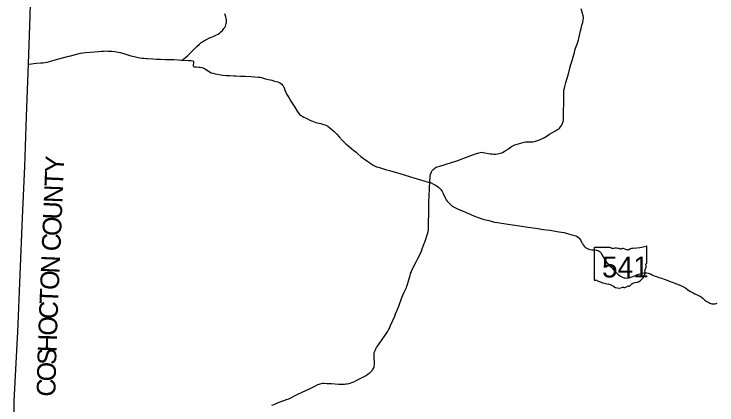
# Model space of a CAD drawing. Extents: x 1913970 to 2276415, y 78841 to 927181.
# Drawn here: x 2053316 to 2090901, y 816112 to 837024 of the extents above; entities that cross this region are included whole.
import ezdxf

# ---------------------------------------------------------------- set-up
doc = ezdxf.new("R2010")
doc.units = 0
for name, color, linetype in [('GM_X_County', 7, 'Continuous'), ('GM_X_County_Text', 7, 'Continuous'), ('GM_X_State_Location', 7, 'Continuous'), ('GM_X_State_Route', 7, 'Continuous'), ('GM_X_State_Shield', 7, 'Continuous')]:
    doc.layers.add(name, color=color, linetype=linetype)

msp = doc.modelspace()

# ---------------------------------------------------------------- linework, layer by layer
at = {"layer": 'GM_X_County'}
msp.add_lwpolyline([(2053316, 815692), (2053322, 816320), (2053497, 819709), (2053518, 820007), (2053767, 826144), (2053891, 828875), (2053973, 831537), (2054094, 834355), (2054174, 836926), (2054221, 838228)], dxfattribs=at)
at = {"layer": 'GM_X_State_Route'}
for points in [[(2062328, 834559), (2062398, 834622), (2062467, 834679), (2062601, 834812), (2062783, 834988), (2062951, 835153), (2063089, 835286), (2063229, 835416), (2063323, 835495), (2063385, 835540), (2063472, 835598), (2063563, 835650), (2063638, 835689), (2063768, 835748), (2063956, 835825), (2064140, 835905), (2064231, 835954), (2064294, 835996), (2064381, 836067), (2064455, 836140), (2064541, 836243), (2064584, 836309), (2064619, 836382), (2064643, 836450), (2064663, 836523), (2064669, 836578), (2064676, 836661), (2064672, 836720), (2064662, 836776), (2064635, 836879), (2064592, 837027)], [(2082484, 830928), (2082535, 830985), (2082589, 831056), (2082610, 831094), (2082639, 831150), (2082660, 831214), (2082678, 831279), (2082689, 831361), (2082691, 831457), (2082697, 831769), (2082705, 831966), (2082710, 832120), (2082713, 832392), (2082711, 832724), (2082713, 832834), (2082720, 832923), (2082733, 832999), (2082749, 833068), (2082770, 833147), (2082830, 833365), (2082963, 833834), (2083024, 834052), (2083097, 834321), (2083160, 834541), (2083227, 834788), (2083277, 834974), (2083305, 835071), (2083347, 835196), (2083445, 835472), (2083494, 835643), (2083515, 835722), (2083553, 835879), (2083607, 836133), (2083636, 836248), (2083685, 836424), (2083726, 836575), (2083752, 836716), (2083759, 836787), (2083759, 836845), (2083748, 836925), (2083647, 837301)], [(2054095, 834352), (2054245, 834366), (2054371, 834375), (2054516, 834389), (2054746, 834407), (2054852, 834417), (2054968, 834432), (2055085, 834458), (2055211, 834487), (2055341, 834522), (2055462, 834556), (2055648, 834606), (2056249, 834765), (2056359, 834793), (2056538, 834842), (2056862, 834923), (2056987, 834949), (2057138, 834967), (2057392, 834988), (2057610, 835003), (2057833, 835019), (2057993, 835035), (2058107, 835044), (2058202, 835048), (2058347, 835047), (2058448, 835041), (2058559, 835030), (2058706, 835012), (2058891, 834984), (2058997, 834961), (2059180, 834910), (2059461, 834825), (2059567, 834794), (2059652, 834771), (2059738, 834750), (2059816, 834729), (2059944, 834696), (2060036, 834679), (2060149, 834666), (2060262, 834656), (2060403, 834649), (2060458, 834645), (2060752, 834629), (2060935, 834617), (2061144, 834607), (2061418, 834601), (2061609, 834594), (2061858, 834584), (2062095, 834571), (2062246, 834564), (2062328, 834559)], [(2062328, 834559), (2062646, 834541), (2062793, 834533), (2062869, 834527), (2062901, 834514)], [(2062901, 834514), (2062910, 834475), (2062907, 834392), (2062895, 834299), (2062897, 834254), (2062907, 834228)], [(2062907, 834228), (2062930, 834205), (2062967, 834197), (2063062, 834193), (2063191, 834186), (2063275, 834176), (2063367, 834158), (2063438, 834135), (2063492, 834109), (2063560, 834067), (2063698, 833979), (2063775, 833931), (2063862, 833884), (2063954, 833853), (2064063, 833826), (2064181, 833803), (2064366, 833779), (2064485, 833762), (2064675, 833743), (2064856, 833733), (2065068, 833722), (2065183, 833716), (2065430, 833707), (2065683, 833697), (2065980, 833683), (2066198, 833669), (2066367, 833656), (2066469, 833640), (2066542, 833626), (2066659, 833595), (2066765, 833566), (2066903, 833531), (2067023, 833500), (2067108, 833480), (2067248, 833440), (2067424, 833390), (2067515, 833357), (2067569, 833327), (2067630, 833277), (2067671, 833228), (2067709, 833177), (2067744, 833109), (2067772, 833030), (2067818, 832900), (2067844, 832839), (2067904, 832724), (2068001, 832560), (2068122, 832367), (2068333, 832041), (2068462, 831836), (2068551, 831703), (2068586, 831657), (2068631, 831613), (2068664, 831589), (2068715, 831562), (2068813, 831513), (2068905, 831468), (2069038, 831398), (2069172, 831330), (2069270, 831287), (2069355, 831254), (2069445, 831227), (2069712, 831161), (2069809, 831138), (2069941, 831098), (2070015, 831064), (2070089, 831020), (2070177, 830957), (2070328, 830832), (2070415, 830755), (2070576, 830592), (2070699, 830459), (2070862, 830282), (2070982, 830161), (2071062, 830086), (2071149, 830009), (2071251, 829926), (2071359, 829837), (2071493, 829728), (2071607, 829630), (2071702, 829547), (2071861, 829412), (2071998, 829301), (2072109, 829219), (2072239, 829131), (2072394, 829025), (2072488, 828963), (2072568, 828918), (2072630, 828886), (2072693, 828859), (2072792, 828825), (2072911, 828789), (2073179, 828711), (2073401, 828650), (2073567, 828602), (2073893, 828506), (2074229, 828403), (2074454, 828337), (2074572, 828301), (2074686, 828266), (2074870, 828210), (2075050, 828158), (2075181, 828117), (2075287, 828086), (2075398, 828053), (2075548, 828015)], [(2072553, 818091), (2072567, 818142), (2072580, 818204), (2072588, 818275), (2072589, 818365), (2072585, 818434), (2072572, 818590), (2072568, 818727), (2072578, 818863), (2072599, 818955), (2072622, 819017), (2072669, 819113), (2072705, 819179), (2072809, 819335), (2073006, 819622), (2073119, 819785), (2073216, 819920), (2073291, 820030), (2073347, 820124), (2073383, 820190), (2073453, 820366), (2073669, 820867), (2073720, 820984), (2073804, 821186), (2073887, 821405), (2074059, 821859), (2074111, 821991), (2074171, 822138), (2074293, 822401), (2074322, 822472), (2074349, 822555), (2074423, 822805), (2074459, 822930), (2074491, 823037), (2074523, 823137), (2074560, 823238), (2074593, 823321), (2074819, 823775), (2074908, 823947), (2075041, 824215), (2075098, 824343), (2075145, 824457), (2075200, 824601), (2075316, 824923), (2075414, 825207), (2075435, 825300), (2075458, 825391), (2075469, 825486), (2075475, 825599), (2075478, 825760), (2075485, 826023), (2075493, 826205), (2075495, 826479), (2075502, 826810), (2075520, 827446), (2075524, 827548), (2075534, 827768), (2075548, 828015), (2075554, 828086), (2075565, 828282), (2075570, 828346), (2075585, 828437), (2075596, 828490), (2075614, 828536), (2075638, 828586), (2075676, 828649), (2075723, 828707), (2075772, 828752), (2075833, 828798), (2075889, 828827), (2075947, 828852), (2076078, 828894), (2076369, 828984), (2076765, 829102), (2076935, 829152), (2077100, 829207), (2077233, 829257), (2077652, 829416), (2077991, 829540), (2078174, 829606), (2078249, 829623), (2078330, 829627), (2078396, 829622), (2078489, 829606), (2078678, 829570), (2078776, 829552), (2078886, 829539), (2078960, 829534), (2079057, 829534), (2079160, 829543), (2079251, 829558), (2079326, 829573), (2079397, 829601), (2079442, 829621), (2079524, 829666), (2079633, 829735), (2079748, 829818), (2079850, 829892), (2079911, 829933), (2079996, 829977), (2080097, 830020), (2080221, 830066), (2080337, 830102), (2080472, 830138), (2080599, 830166), (2080689, 830182), (2080801, 830196), (2080891, 830197), (2081003, 830194), (2081048, 830197), (2081141, 830211), (2081244, 830242), (2081369, 830280), (2081446, 830308), (2081534, 830345), (2081605, 830379), (2081684, 830425), (2081823, 830510), (2081952, 830590), (2082108, 830686), (2082232, 830757), (2082344, 830822), (2082406, 830864), (2082459, 830905), (2082484, 830928)], [(2075548, 828015), (2075576, 828009), (2075627, 827991), (2075745, 827932), (2075854, 827871), (2075938, 827816), (2076013, 827759), (2076074, 827701), (2076136, 827630), (2076201, 827540), (2076268, 827418), (2076377, 827187), (2076430, 827091), (2076484, 827014), (2076548, 826935), (2076613, 826867), (2076688, 826799), (2076745, 826755), (2076821, 826704), (2076919, 826654), (2077066, 826589), (2077291, 826497), (2077499, 826407), (2077714, 826312), (2077941, 826218), (2078133, 826145), (2078243, 826107), (2078390, 826059), (2078613, 825994), (2078695, 825971), (2078824, 825939), (2079002, 825899), (2079168, 825870), (2079615, 825805), (2079966, 825751), (2080345, 825695), (2080691, 825639), (2080812, 825623)], [(2080812, 825623), (2081318, 825550), (2081621, 825507), (2081969, 825454), (2082473, 825376), (2082715, 825333), (2082903, 825288), (2083140, 825218), (2083364, 825151), (2083432, 825116), (2083490, 825076), (2083535, 825035), (2083586, 824971), (2083621, 824912), (2083675, 824793), (2083707, 824741), (2083751, 824670), (2083798, 824615), (2083851, 824561), (2083905, 824518), (2083974, 824474), (2084059, 824439), (2084128, 824425), (2084210, 824415), (2084286, 824413), (2084387, 824404), (2084464, 824394), (2084518, 824378), (2084568, 824360), (2084602, 824343), (2084649, 824304), (2084684, 824271), (2084704, 824239), (2084734, 824179), (2084809, 824034), (2084887, 823894), (2084923, 823835), (2084975, 823765), (2085029, 823706), (2085077, 823656), (2085136, 823588), (2085180, 823541), (2085228, 823497), (2085319, 823409), (2085396, 823327), (2085532, 823180), (2085605, 823108), (2085671, 823049), (2085745, 822996), (2085821, 822958), (2085890, 822931), (2085940, 822918), (2085999, 822908), (2086066, 822902), (2086138, 822907), (2086202, 822921), (2086284, 822945), (2086414, 822990), (2086625, 823065), (2086733, 823102), (2086849, 823140), (2086921, 823164), (2086993, 823179), (2087072, 823185), (2087158, 823183), (2087219, 823171), (2087283, 823147), (2087346, 823120), (2087432, 823079), (2087515, 823038), (2087602, 823003), (2087676, 822976), (2087796, 822932), (2087929, 822890), (2088125, 822822), (2088357, 822735), (2088737, 822586), (2088962, 822498), (2089037, 822468), (2089107, 822434), (2089180, 822396), (2089244, 822357), (2089327, 822295), (2089404, 822239), (2089490, 822181), (2089624, 822106), (2089725, 822052), (2089841, 821999), (2089949, 821952), (2090000, 821928), (2090049, 821900), (2090099, 821863), (2090150, 821818), (2090275, 821702), (2090330, 821664), (2090396, 821624), (2090467, 821585), (2090523, 821560), (2090580, 821539), (2090634, 821527), (2090692, 821522), (2090751, 821522), (2090804, 821529), (2090860, 821545), (2090907, 821562)], [(2072163, 817713), (2072257, 817783), (2072355, 817855), (2072410, 817901), (2072457, 817947), (2072490, 817989), (2072527, 818042), (2072553, 818091)], [(2067102, 816097), (2067217, 816145), (2067400, 816219), (2067537, 816271), (2067879, 816395), (2068005, 816446), (2068115, 816498), (2068310, 816594), (2068495, 816684), (2068720, 816794), (2069112, 816980), (2069434, 817138), (2069566, 817203), (2069629, 817231), (2069687, 817250), (2069752, 817265), (2069806, 817272), (2069892, 817272), (2070036, 817266), (2070289, 817253), (2070662, 817231), (2070836, 817223), (2070928, 817225), (2070994, 817229), (2071068, 817235), (2071130, 817246), (2071220, 817266), (2071283, 817284), (2071374, 817314), (2071482, 817357), (2071618, 817422), (2071789, 817501), (2071936, 817576), (2072032, 817628), (2072108, 817676), (2072163, 817713)]]:
    msp.add_lwpolyline(points, dxfattribs=at)
at = {"layer": 'GM_X_State_Shield'}
for p, q in [((2084343, 824514), (2084343, 822813)), ((2085191, 824544), (2084371, 824544)), ((2087145, 823696), (2087145, 824586)), ((2087145, 823696), (2087145, 823696))]:
    msp.add_line(p, q, dxfattribs=at)
for centre, major_axis, start_param, end_param in [((2084375, 824518), (32.5, 0), 1.712693, 3.28349), ((2085387, 824741), (315, 0), 4.042523, 4.731795), ((2085491, 823589), (1130, 0), 1.404758, 1.657858), ((2085748, 824527), (90.8, 0), 3.836095, 5.185415), ((2085881, 824330), (189, 0), 0.950623, 2.079405), ((2086125, 824600), (227, 0), 4.081561, 5.145723), ((2086526, 824024), (598, 0), 1.699011, 2.107814), ((2086147, 826863), (2971, 0), 4.814394, 5.042369), ((2087114, 824590), (31.2, 0), 6.141152, 7.989035), ((2087138, 823631), (48.3, 0), 1.883978, 3.671073), ((2086831, 823518), (290, 0), 5.934695, 6.695948), ((2087112, 823693), (33.4, 0), 5.05454, 6.418171), ((2086313, 823210), (743, 0), 5.101752, 6.440018), ((2087257, 823324), (211, 0), 2.387724, 3.262537), ((2084376, 822810), (32.7, 0), 3.00124, 4.508301), ((2084380, 822984), (250, 0), 4.665946, 4.897461), ((2084432, 822715), (90.1, 0), 0.519207, 1.627899), ((2085569, 824244), (2146, 0), 4.195997, 4.488961), ((2084930, 822049), (671, 0), 0.823519, 1.323587), ((2085656, 822707), (426, 0), 4.026481, 4.996735), ((2085902, 822119), (350, 0), 1.495662, 1.94098), ((2085933, 822579), (227, 0), 4.691044, 5.507374), ((2086138, 822415), (63.9, 0), 1.147584, 2.315152), ((2086111, 822648), (240, 0), 4.937069, 5.64225), ((2086627, 822336), (407, 0), 1.647645, 2.488434)]:
    msp.add_ellipse(centre, major_axis=major_axis, ratio=0.8, start_param=start_param, end_param=end_param, dxfattribs=at)

# ---------------------------------------------------------------- texts
at = {"layer": 'GM_X_County_Text'}
for s, rotation, p in [('Y', 87.5777, (2055969, 828531)), ('T', 87.5775, (2055938, 827783)), ('N', 87.5777, (2055900, 826900)), ('U', 87.5777, (2055863, 826016)), ('O', 87.5782, (2055826, 825133)), ('C', 87.5774, (2055791, 824319)), ('N', 87.5787, (2055741, 823132)), ('O', 87.5809, (2055704, 822249)), ('T', 87.6195, (2055673, 821502)), ('C', 87.7345, (2055641, 820689)), ('O', 87.9933, (2055610, 819806)), ('H', 88.1468, (2055581, 818923)), ('S', 88.4429, (2055563, 818247)), ('O', 88.6221, (2055541, 817364)), ('C', 88.7003, (2055523, 816550))]:
    msp.add_text(s, height=1000, rotation=rotation, dxfattribs=at).set_placement(p)
at = {"layer": 'GM_X_State_Location'}
for s in ['s', 'r']:
    msp.add_text(s, height=1, dxfattribs=at).set_placement((2085478, 823179))
msp.add_text('541', height=1, rotation=0, dxfattribs=at).set_placement((2085125, 823106))
at = {"layer": 'GM_X_State_Shield'}
msp.add_text('541', height=1120.7, dxfattribs=at).set_placement((2084756, 822933))

doc.saveas('drawing.dxf')
